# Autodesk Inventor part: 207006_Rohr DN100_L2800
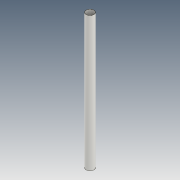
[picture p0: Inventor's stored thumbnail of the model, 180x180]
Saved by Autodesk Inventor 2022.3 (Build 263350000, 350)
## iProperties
Created: 2022-07
Part Number: 207006_Rohr DN100_L2800
Material: Stahl, unlegiert
Document SubType Name: Modeling
Designer: PDM-USER
Mass: 15509.1 g
Surface Area: 19771 cm^2
Volume: 1975.68 cm^3
Density: 7.85 g/cm^3
Appearance: Stahl
Author: PDM-USER
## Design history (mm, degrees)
sketch "Skizze1"
  geometry: C1 r 57.15 at (0, 0); C2 r 55.15 at (0, 0); 1 further point
  constraints: 2 centre point, 2 coincident
  dimensions: "d0" = 114.3 diameter of C1; "d1" = 2 radial gap between concentric circles of C1 C2
extrude "Extrusion1" new body sketch "Skizze1" distance "d2" = 1949; taper "d3" = 0 deg
node "Volumenkörper1"
